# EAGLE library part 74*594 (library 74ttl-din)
8-bit SHIFT REGISTER, output latch
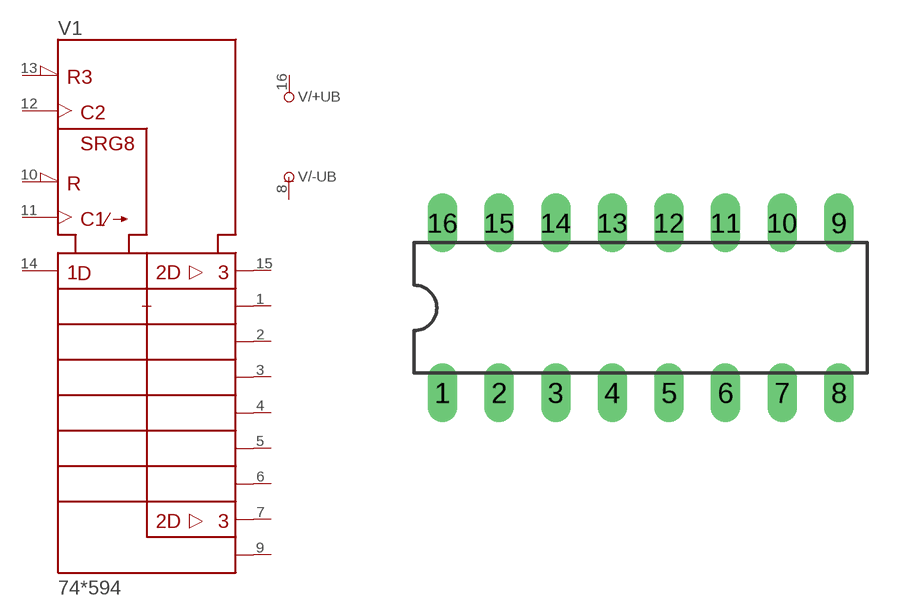
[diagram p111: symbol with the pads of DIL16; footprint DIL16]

Designator prefix V; gates /+UB=+UB /-UB=-UB 1=594

## 74594N  [DIL16]
1  1:QB  hiz
2  1:QC  hiz
3  1:QD  hiz
4  1:QE  hiz
5  1:QF  hiz
6  1:QG  hiz
7  1:QH  hiz
8  /-UB:-UB  pwr
9  1:QH*  out
10  1:SRCLR\  in
11  1:SRCK  in
12  1:RCK  in
13  1:RCLR\  in
14  1:SER  in
15  1:QA  hiz
16  /+UB:+UB  pwr

## Footprint DIL16 (pad centres in mm)
Dual In Line Package
drill 0.813 long: 1 -8.89,-3.81; 2 -6.35,-3.81; 3 -3.81,-3.81; 4 -1.27,-3.81; 5 1.27,-3.81; 6 3.81,-3.81; 7 6.35,-3.81; 8 8.89,-3.81; 9 8.89,3.81; 10 6.35,3.81; 11 3.81,3.81; 12 1.27,3.81; 13 -1.27,3.81; 14 -3.81,3.81; 15 -6.35,3.81; 16 -8.89,3.81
